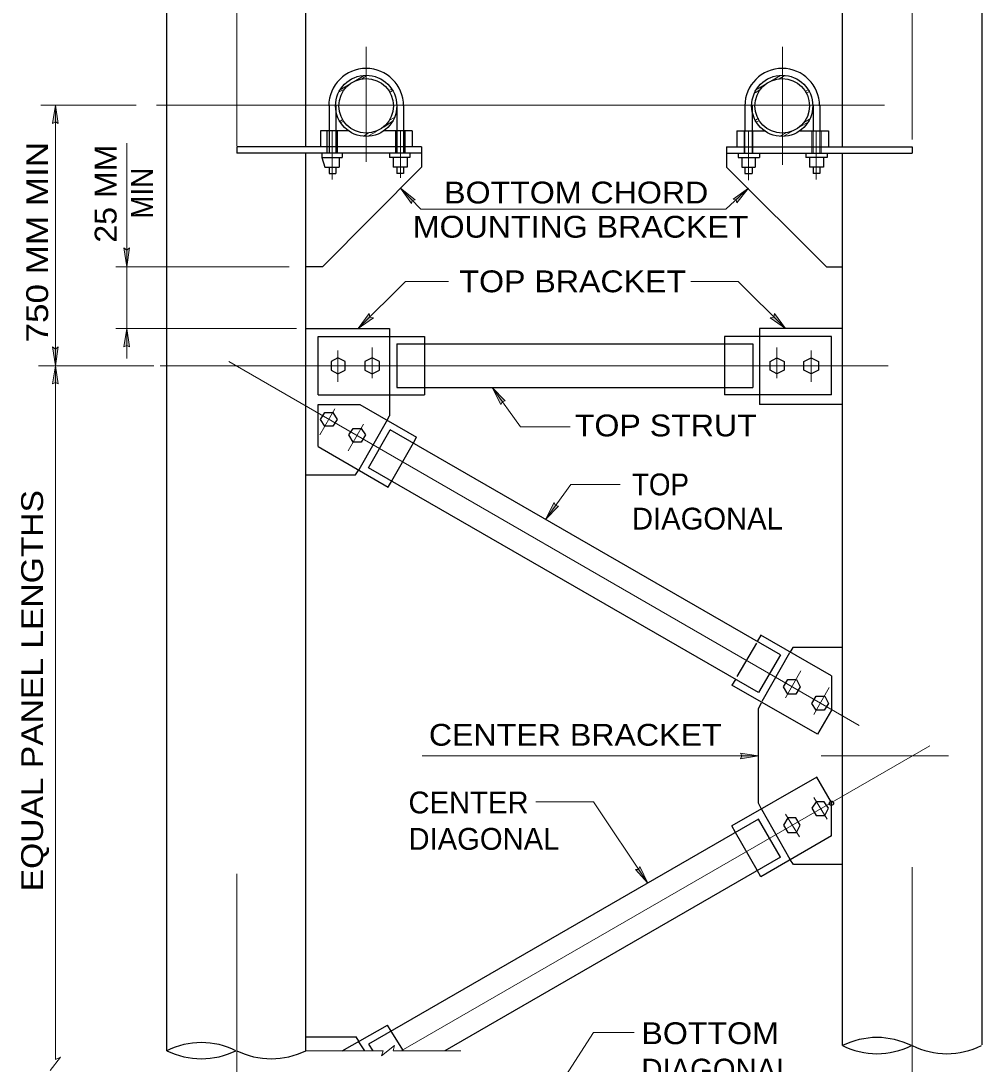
# Model space of a CAD drawing. Extents: x 312601.858 to 312602.699, y 144420.109 to 144420.704.
# Drawn here: x 312601.9368 to 312602.0688, y 144420.4227 to 144420.566 of the extents above; entities that cross this region are included whole.
import ezdxf
from ezdxf.enums import TextEntityAlignment as Align

# ---------------------------------------------------------------- set-up
doc = ezdxf.new("R2010")
doc.units = 0
doc.header["$LTSCALE"] = 0.0012
doc.header["$PDMODE"] = 32
doc.header["$PDSIZE"] = 0.0006
for name, pattern in [('DOT_DASHED', [7.7, 5, -1.2, 0.3, -1.2]), ('LONG_DASHED', [7.5, 6, -1.5]), ('MEDIUM_DASHED', [4.5, 3, -1.5])]:
    doc.linetypes.add(name, pattern=pattern)
for name, color, linetype, lineweight in [('1', 7, 'Continuous', 25), ('2', 7, 'Continuous', 13), ('39', 7, 'Continuous', 13)]:
    doc.layers.add(name, color=color, linetype=linetype, lineweight=lineweight)

msp = doc.modelspace()

# ---------------------------------------------------------------- hatches: boundary and pattern name
at = {"layer": '39'}
for points in [[(312601.9415, 144420.5521), (312601.9411, 144420.5519), (312601.9415, 144420.5544), (312601.9419, 144420.5519)], [(312601.9905, 144420.5413), (312601.9904, 144420.5409), (312601.9889, 144420.543), (312601.9909, 144420.5414)], [(312602.035, 144420.5414), (312602.0346, 144420.5415), (312602.0367, 144420.543), (312602.0351, 144420.541)], [(312601.9513, 144420.5345), (312601.9517, 144420.5348), (312601.9513, 144420.5322), (312601.9509, 144420.5348)], [(312601.9847, 144420.5253), (312601.9852, 144420.5252), (312601.9831, 144420.5237), (312601.9846, 144420.5258)], [(312602.0402, 144420.5253), (312602.0403, 144420.5258), (312602.0418, 144420.5237), (312602.0397, 144420.5252)], [(312601.9513, 144420.5214), (312601.9509, 144420.5212), (312601.9513, 144420.5237), (312601.9517, 144420.5212)], [(312601.9415, 144420.5209), (312601.9419, 144420.5212), (312601.9415, 144420.5186), (312601.9411, 144420.5212)], [(312601.9415, 144420.5163), (312601.9411, 144420.5161), (312601.9415, 144420.5186), (312601.9419, 144420.5161)], [(312602.0029, 144420.5137), (312602.0027, 144420.5133), (312602.0015, 144420.5156), (312602.0033, 144420.5138)], [(312602.0102, 144420.4994), (312602.0106, 144420.4993), (312602.0088, 144420.4975), (312602.01, 144420.4998)], [(312602.0358, 144420.465), (312602.0356, 144420.4654), (312602.0381, 144420.465), (312602.0356, 144420.4646)], [(312602.0216, 144420.4494), (312602.0218, 144420.4498), (312602.0229, 144420.4475), (312602.0212, 144420.4494)], [(312602.0216, 144420.4494), (312602.0218, 144420.4498), (312602.0229, 144420.4475), (312602.0212, 144420.4494)]]:
    msp.add_hatch(color=256, dxfattribs=at).paths.add_polyline_path(points)

# ---------------------------------------------------------------- linework, layer by layer
at = {"layer": '1'}
for p, q in [((312601.9568, 144420.4245), (312601.9568, 144420.6043)), ((312601.9759, 144420.5487), (312601.9759, 144420.6043)), ((312602.0496, 144420.5487), (312602.0496, 144420.6043)), ((312602.0688, 144420.4253), (312602.0688, 144420.6044)), ((312601.9791, 144420.5544), (312601.9791, 144420.5509)), ((312601.98, 144420.5544), (312601.98, 144420.5509)), ((312601.9884, 144420.5544), (312601.9884, 144420.5509)), ((312601.9893, 144420.5544), (312601.9893, 144420.5509)), ((312602.0362, 144420.5544), (312602.0362, 144420.5509)), ((312602.0372, 144420.5544), (312602.0372, 144420.5509)), ((312602.0456, 144420.5544), (312602.0456, 144420.5509)), ((312602.0465, 144420.5544), (312602.0465, 144420.5509)), ((312601.9818, 144420.5509), (312601.9779, 144420.5509)), ((312601.9779, 144420.5509), (312601.9779, 144420.5487)), ((312601.9905, 144420.5509), (312601.9866, 144420.5509)), ((312601.9905, 144420.5509), (312601.9905, 144420.5487)), ((312602.0351, 144420.5509), (312602.0389, 144420.5509)), ((312602.0351, 144420.5509), (312602.0351, 144420.5487)), ((312602.0438, 144420.5509), (312602.0477, 144420.5509)), ((312602.0477, 144420.5509), (312602.0477, 144420.5487)), ((312601.9918, 144420.5487), (312601.9664, 144420.5487)), ((312601.9664, 144420.5487), (312601.9664, 144420.5478)), ((312601.9918, 144420.5487), (312601.9918, 144420.5459)), ((312602.0337, 144420.5487), (312602.0592, 144420.5487)), ((312602.0337, 144420.5487), (312602.0337, 144420.5459)), ((312602.0592, 144420.5487), (312602.0592, 144420.5478)), ((312601.9918, 144420.5478), (312601.9664, 144420.5478)), ((312601.9759, 144420.4245), (312601.9759, 144420.5478)), ((312601.9781, 144420.5472), (312601.9809, 144420.5472)), ((312601.9805, 144420.5472), (312601.9805, 144420.5459)), ((312601.9809, 144420.5478), (312601.9809, 144420.5472)), ((312601.9874, 144420.5478), (312601.9874, 144420.5472)), ((312601.9902, 144420.5472), (312601.9874, 144420.5472)), ((312601.9879, 144420.5472), (312601.9879, 144420.5459)), ((312601.9898, 144420.5472), (312601.9898, 144420.5459)), ((312601.9902, 144420.5478), (312601.9902, 144420.5472)), ((312602.0337, 144420.5478), (312602.0592, 144420.5478)), ((312602.0353, 144420.5478), (312602.0353, 144420.5472)), ((312602.0353, 144420.5472), (312602.0382, 144420.5472)), ((312602.0358, 144420.5472), (312602.0358, 144420.5459)), ((312602.0376, 144420.5472), (312602.0376, 144420.5459)), ((312602.0382, 144420.5478), (312602.0382, 144420.5472)), ((312602.0446, 144420.5478), (312602.0446, 144420.5472)), ((312602.0475, 144420.5472), (312602.0446, 144420.5472)), ((312602.0451, 144420.5472), (312602.0451, 144420.5459)), ((312602.047, 144420.5472), (312602.047, 144420.5459)), ((312602.0475, 144420.5478), (312602.0475, 144420.5472)), ((312602.0496, 144420.4252), (312602.0496, 144420.5478)), ((312601.9782, 144420.5322), (312601.9918, 144420.5459)), ((312601.9785, 144420.5459), (312601.9805, 144420.5459)), ((312601.9791, 144420.5459), (312601.9791, 144420.545)), ((312601.98, 144420.5459), (312601.98, 144420.545)), ((312601.9898, 144420.5459), (312601.9879, 144420.5459)), ((312601.9884, 144420.5459), (312601.9884, 144420.545)), ((312601.9893, 144420.5459), (312601.9893, 144420.545)), ((312602.0474, 144420.5322), (312602.0337, 144420.5459)), ((312602.0358, 144420.5459), (312602.0376, 144420.5459)), ((312602.0362, 144420.5459), (312602.0362, 144420.545)), ((312602.0372, 144420.5459), (312602.0372, 144420.545)), ((312602.047, 144420.5459), (312602.0451, 144420.5459)), ((312602.0456, 144420.5459), (312602.0456, 144420.545)), ((312602.0465, 144420.5459), (312602.0465, 144420.545)), ((312601.9791, 144420.545), (312601.98, 144420.545)), ((312601.9893, 144420.545), (312601.9884, 144420.545)), ((312602.0362, 144420.545), (312602.0372, 144420.545)), ((312602.0465, 144420.545), (312602.0456, 144420.545)), ((312601.9782, 144420.5322), (312601.9759, 144420.5322)), ((312602.0474, 144420.5322), (312602.0496, 144420.5322)), ((312601.9759, 144420.5237), (312601.9874, 144420.5237)), ((312601.9874, 144420.5237), (312601.9874, 144420.5226)), ((312602.0496, 144420.5237), (312602.0382, 144420.5237)), ((312602.0382, 144420.5237), (312602.0382, 144420.5226)), ((312601.9776, 144420.5226), (312601.9922, 144420.5226)), ((312601.9776, 144420.5146), (312601.9776, 144420.5226)), ((312601.9922, 144420.5226), (312601.9922, 144420.5216)), ((312602.0481, 144420.5226), (312602.0334, 144420.5226)), ((312602.0334, 144420.5226), (312602.0334, 144420.5216)), ((312602.0481, 144420.5146), (312602.0481, 144420.5226)), ((312601.9884, 144420.5216), (312602.0373, 144420.5216)), ((312601.9884, 144420.5216), (312601.9884, 144420.5156)), ((312602.0373, 144420.5216), (312602.0373, 144420.5156)), ((312601.9884, 144420.5156), (312602.0373, 144420.5156)), ((312601.9922, 144420.5156), (312601.9922, 144420.5146)), ((312602.0334, 144420.5156), (312602.0334, 144420.5146)), ((312601.9776, 144420.5146), (312601.9922, 144420.5146)), ((312601.9874, 144420.5146), (312601.9874, 144420.5117)), ((312602.0481, 144420.5146), (312602.0334, 144420.5146)), ((312602.0382, 144420.5146), (312602.0382, 144420.5133)), ((312601.9776, 144420.5075), (312601.9776, 144420.5133)), ((312601.9776, 144420.5133), (312601.9833, 144420.5133)), ((312601.9833, 144420.5133), (312601.9911, 144420.5088)), ((312602.0496, 144420.5133), (312602.0382, 144420.5133)), ((312601.9871, 144420.5112), (312601.9874, 144420.5117)), ((312601.9845, 144420.5046), (312601.9875, 144420.5098)), ((312602.0411, 144420.4789), (312601.9875, 144420.5098)), ((312601.9907, 144420.508), (312601.9911, 144420.5088)), ((312601.9776, 144420.5075), (312601.9872, 144420.5019)), ((312601.9759, 144420.5036), (312601.9827, 144420.5036)), ((312601.9827, 144420.5036), (312601.9832, 144420.5043)), ((312602.0381, 144420.4737), (312601.9845, 144420.5046)), ((312601.9872, 144420.5019), (312601.9877, 144420.5028)), ((312602.0384, 144420.4816), (312602.0379, 144420.4807)), ((312602.0481, 144420.476), (312602.0384, 144420.4816)), ((312602.0428, 144420.4799), (312602.0424, 144420.4792)), ((312602.0496, 144420.4799), (312602.0428, 144420.4799)), ((312602.0411, 144420.4789), (312602.0381, 144420.4737)), ((312602.0349, 144420.4755), (312602.0344, 144420.4747)), ((312602.0481, 144420.476), (312602.0481, 144420.4713)), ((312602.0462, 144420.468), (312602.0344, 144420.4747)), ((312602.0381, 144420.4715), (312602.0385, 144420.4723)), ((312602.0381, 144420.4585), (312602.0381, 144420.4715)), ((312602.0481, 144420.4713), (312602.0462, 144420.468)), ((312602.0461, 144420.4621), (312602.0344, 144420.4554)), ((312602.0481, 144420.4586), (312602.0461, 144420.4621)), ((312602.0385, 144420.4577), (312602.0381, 144420.4585)), ((312602.0481, 144420.454), (312602.0481, 144420.4586)), ((312602.0381, 144420.4563), (312601.9845, 144420.4254)), ((312602.0411, 144420.4511), (312602.0381, 144420.4563)), ((312602.0349, 144420.4545), (312602.0344, 144420.4554)), ((312602.0481, 144420.454), (312602.0384, 144420.4484)), ((312602.0411, 144420.4511), (312601.995, 144420.4245)), ((312602.0429, 144420.4501), (312602.0424, 144420.4508)), ((312602.0384, 144420.4484), (312602.0379, 144420.4493)), ((312602.0496, 144420.4501), (312602.0429, 144420.4501)), ((312601.9809, 144420.4245), (312601.9871, 144420.428)), ((312601.9876, 144420.4272), (312601.9871, 144420.428)), ((312601.9759, 144420.4264), (312601.9828, 144420.4264)), ((312601.9832, 144420.4258), (312601.9828, 144420.4264)), ((312601.9845, 144420.4254), (312601.9851, 144420.4245))]:
    msp.add_line(p, q, dxfattribs=at)
at = {"layer": '1', "linetype": 'DOT_DASHED', "lineweight": 13}
for p, q in [((312601.9842, 144420.5624), (312601.9842, 144420.5466)), ((312602.0414, 144420.5624), (312602.0414, 144420.5462)), ((312601.9554, 144420.5544), (312602.0637, 144420.5544)), ((312601.9795, 144420.5442), (312601.9795, 144420.5509)), ((312601.9889, 144420.5444), (312601.9889, 144420.5509)), ((312602.0367, 144420.5441), (312602.0367, 144420.5509)), ((312602.046, 144420.5442), (312602.046, 144420.5509)), ((312601.985, 144420.5169), (312601.985, 144420.5211)), ((312602.0406, 144420.5169), (312602.0406, 144420.5211)), ((312601.9803, 144420.5164), (312601.9803, 144420.5207)), ((312602.0453, 144420.5164), (312602.0453, 144420.5207)), ((312601.9559, 144420.5186), (312602.062, 144420.5186)), ((312601.9653, 144420.5192), (312602.0616, 144420.4636)), ((312601.9799, 144420.5127), (312601.9778, 144420.5091)), ((312601.9838, 144420.5106), (312601.9817, 144420.5069)), ((312602.0418, 144420.473), (312602.0439, 144420.4767)), ((312602.0457, 144420.4707), (312602.0478, 144420.4744)), ((312601.989, 144420.4245), (312602.0616, 144420.4664)), ((312602.0467, 144420.465), (312602.0642, 144420.465)), ((312602.0457, 144420.4593), (312602.0475, 144420.4563)), ((312602.0418, 144420.457), (312602.0437, 144420.4539))]:
    msp.add_line(p, q, dxfattribs=at)
at = {"layer": '1', "lineweight": 13}
for p, q in [((312601.9806, 144420.5565), (312601.9839, 144420.5585)), ((312601.9836, 144420.558), (312601.9843, 144420.5585)), ((312602.0379, 144420.5566), (312602.0411, 144420.5585)), ((312602.0409, 144420.558), (312602.0417, 144420.5585)), ((312601.9804, 144420.5562), (312601.9812, 144420.5566)), ((312601.9873, 144420.5564), (312601.9877, 144420.5566)), ((312602.0376, 144420.5561), (312602.0384, 144420.5566)), ((312601.9875, 144420.5562), (312601.9878, 144420.5564)), ((312602.0445, 144420.5563), (312602.0449, 144420.5565)), ((312602.0447, 144420.5561), (312602.0451, 144420.5563)), ((312601.9395, 144420.5544), (312601.9526, 144420.5544)), ((312601.9806, 144420.5522), (312601.9809, 144420.5524)), ((312601.9873, 144420.5523), (312601.9881, 144420.5527)), ((312602.0376, 144420.5523), (312602.0381, 144420.5526)), ((312602.0378, 144420.5521), (312602.0382, 144420.5523)), ((312602.0443, 144420.552), (312602.0451, 144420.5525)), ((312601.9807, 144420.552), (312601.9811, 144420.5522)), ((312601.9866, 144420.5514), (312601.9878, 144420.5522)), ((312602.0416, 144420.5502), (312602.0448, 144420.552)), ((312601.9839, 144420.5502), (312601.9845, 144420.5506)), ((312601.9845, 144420.5502), (312601.9856, 144420.5508)), ((312602.0411, 144420.5502), (312602.0419, 144420.5506)), ((312601.9889, 144420.543), (312601.9917, 144420.5401)), ((312602.0336, 144420.5401), (312602.0367, 144420.543)), ((312601.9917, 144420.5401), (312602.0336, 144420.5401)), ((312601.9736, 144420.5322), (312601.9498, 144420.5322)), ((312601.9831, 144420.5237), (312601.9896, 144420.5302)), ((312601.9896, 144420.5302), (312601.9955, 144420.5302)), ((312602.0288, 144420.5302), (312602.0353, 144420.5302)), ((312602.0418, 144420.5237), (312602.0353, 144420.5302)), ((312601.9498, 144420.5237), (312601.9746, 144420.5237)), ((312601.9513, 144420.5237), (312601.9513, 144420.5196)), ((312601.9392, 144420.5186), (312601.955, 144420.5186)), ((312602.0054, 144420.5102), (312602.0015, 144420.5156)), ((312602.0054, 144420.5102), (312602.0122, 144420.5102)), ((312602.0088, 144420.4975), (312602.0123, 144420.5023)), ((312602.0123, 144420.5023), (312602.0191, 144420.5023)), ((312601.9919, 144420.465), (312602.0381, 144420.465)), ((312601.9881, 144420.4252), (312601.9863, 144420.4238)), ((312601.9881, 144420.4252), (312601.9879, 144420.4245)), ((312601.9422, 144420.4236), (312601.9408, 144420.4218)), ((312601.9422, 144420.4236), (312601.9415, 144420.4233)), ((312601.9759, 144420.4245), (312601.9865, 144420.4245)), ((312601.9865, 144420.4245), (312601.9863, 144420.4238)), ((312601.9879, 144420.4245), (312601.9972, 144420.4245))]:
    msp.add_line(p, q, dxfattribs=at)
at = {"layer": '1', "linetype": 'LONG_DASHED'}
for p, q in [((312601.9788, 144420.5509), (312601.9788, 144420.5478)), ((312601.9791, 144420.5509), (312601.9791, 144420.5478)), ((312601.98, 144420.5509), (312601.98, 144420.5478)), ((312601.9802, 144420.5509), (312601.9802, 144420.5478)), ((312601.9882, 144420.5509), (312601.9882, 144420.5478)), ((312601.9884, 144420.5509), (312601.9884, 144420.5478)), ((312601.9893, 144420.5509), (312601.9893, 144420.5478)), ((312601.9895, 144420.5509), (312601.9895, 144420.5478))]:
    msp.add_line(p, q, dxfattribs=at)
at = {"layer": '1', "linetype": 'LONG_DASHED', "lineweight": 13}
for p, q in [((312602.0361, 144420.5509), (312602.0361, 144420.5478)), ((312602.0362, 144420.5509), (312602.0362, 144420.5478)), ((312602.0372, 144420.5509), (312602.0372, 144420.5478)), ((312602.0373, 144420.5509), (312602.0373, 144420.5478)), ((312602.0454, 144420.5509), (312602.0454, 144420.5478)), ((312602.0456, 144420.5509), (312602.0456, 144420.5478)), ((312602.0465, 144420.5509), (312602.0465, 144420.5478)), ((312602.0467, 144420.5509), (312602.0467, 144420.5478))]:
    msp.add_line(p, q, dxfattribs=at)
at = {"layer": '1', "linetype": 'MEDIUM_DASHED'}
for p, q in [((312601.9874, 144420.5226), (312601.9874, 144420.5146)), ((312602.0382, 144420.5226), (312602.0382, 144420.5146)), ((312601.9922, 144420.5216), (312601.9922, 144420.5156)), ((312602.0334, 144420.5216), (312602.0334, 144420.5156)), ((312601.9871, 144420.5112), (312601.9832, 144420.5043)), ((312601.9877, 144420.5028), (312601.9907, 144420.508)), ((312602.0378, 144420.4805), (312602.0351, 144420.4759)), ((312602.0386, 144420.4725), (312602.0424, 144420.4792)), ((312602.0385, 144420.4577), (312602.0424, 144420.4508)), ((312602.0379, 144420.4493), (312602.0349, 144420.4545)), ((312601.9893, 144420.4245), (312601.9876, 144420.4272)), ((312601.984, 144420.4245), (312601.9832, 144420.4257))]:
    msp.add_line(p, q, dxfattribs=at)
at = {"layer": '1', "lineweight": 13}
for points in [[(312601.9415, 144420.4233), (312601.9415, 144420.5186), (312601.9415, 144420.5544)], [(312601.9513, 144420.5492), (312601.9513, 144420.5322), (312601.9513, 144420.5237)], [(312602.0075, 144420.4587), (312602.0154, 144420.4587), (312602.0229, 144420.4475)], [(312602.021, 144420.427), (312602.0154, 144420.427), (312602.007, 144420.4139)]]:
    msp.add_lwpolyline(points, dxfattribs=at)
at = {"layer": '1'}
msp.add_lwpolyline([(312601.9781, 144420.5478), (312601.9781, 144420.5472), (312601.9785, 144420.5459)], dxfattribs=at)
for points in [[(312601.9813, 144420.518), (312601.9813, 144420.5192), (312601.9803, 144420.5197), (312601.9794, 144420.5192), (312601.9794, 144420.518), (312601.9803, 144420.5175)], [(312601.986, 144420.518), (312601.986, 144420.5192), (312601.985, 144420.5197), (312601.984, 144420.5192), (312601.984, 144420.518), (312601.985, 144420.5175)], [(312602.0397, 144420.518), (312602.0397, 144420.5192), (312602.0406, 144420.5197), (312602.0416, 144420.5192), (312602.0416, 144420.518), (312602.0406, 144420.5175)], [(312602.0443, 144420.518), (312602.0443, 144420.5192), (312602.0453, 144420.5197), (312602.0463, 144420.5192), (312602.0463, 144420.518), (312602.0453, 144420.5175)], [(312601.9802, 144420.5112), (312601.9796, 144420.5103), (312601.9785, 144420.5103), (312601.9779, 144420.5112), (312601.9785, 144420.5122), (312601.9796, 144420.5122)], [(312601.9841, 144420.5091), (312601.9835, 144420.5081), (312601.9824, 144420.5081), (312601.9818, 144420.5091), (312601.9824, 144420.51), (312601.9835, 144420.51)], [(312602.0415, 144420.4745), (312602.0421, 144420.4755), (312602.0433, 144420.4755), (312602.0438, 144420.4745), (312602.0432, 144420.4735), (312602.0421, 144420.4735)], [(312602.0454, 144420.4722), (312602.046, 144420.4732), (312602.0472, 144420.4732), (312602.0477, 144420.4722), (312602.0471, 144420.4713), (312602.046, 144420.4713)], [(312602.0454, 144420.4578), (312602.046, 144420.4568), (312602.0472, 144420.4568), (312602.0477, 144420.4578), (312602.0471, 144420.4587), (312602.046, 144420.4587)], [(312602.0415, 144420.4555), (312602.0421, 144420.4545), (312602.0433, 144420.4545), (312602.0438, 144420.4555), (312602.0432, 144420.4565), (312602.0421, 144420.4565)]]:
    msp.add_lwpolyline(points, close=True, dxfattribs=at)
for centre, radius in [((312601.984187, 144420.554312), 0.0042), ((312601.984187, 144420.554312), 0.00375), ((312602.041337, 144420.554312), 0.0042), ((312602.041337, 144420.554312), 0.00375)]:
    msp.add_circle(centre, radius, dxfattribs=at)
for centre in [(312601.984187, 144420.554312), (312602.041337, 144420.554312)]:
    msp.add_arc(centre, 0.005137, 0, 180, dxfattribs=at)
msp.add_point((312602.0481, 144420.4585), dxfattribs=at)
at = {"layer": '2', "linetype": 'DOT_DASHED'}
for p, q in [((312602.0592, 144420.3497), (312602.0592, 144420.6313)), ((312601.9664, 144420.3488), (312601.9664, 144420.631))]:
    msp.add_line(p, q, dxfattribs=at)
at = {"layer": '2', "lineweight": 25}
for centre, start, end in [((312602.05435, 144420.415586), 63.70649, 116.29351), ((312601.96155, 144420.414886), 63.70649, 116.29351), ((312602.05435, 144420.434814), 243.70649, 296.29351), ((312602.06395, 144420.434814), 243.70649, 296.29351), ((312601.96155, 144420.434114), 243.70649, 296.29351), ((312601.97115, 144420.434114), 243.70649, 296.29351)]:
    msp.add_arc(centre, 0.010723, start, end, dxfattribs=at)
at = {"layer": '39'}
for points in [[(312601.9415, 144420.5521), (312601.9411, 144420.5519), (312601.9415, 144420.5544), (312601.9419, 144420.5519)], [(312601.9905, 144420.5413), (312601.9904, 144420.5409), (312601.9889, 144420.543), (312601.9909, 144420.5414)], [(312602.035, 144420.5414), (312602.0346, 144420.5415), (312602.0367, 144420.543), (312602.0351, 144420.541)], [(312601.9513, 144420.5345), (312601.9517, 144420.5348), (312601.9513, 144420.5322), (312601.9509, 144420.5348)], [(312601.9847, 144420.5253), (312601.9852, 144420.5252), (312601.9831, 144420.5237), (312601.9846, 144420.5258)], [(312602.0402, 144420.5253), (312602.0403, 144420.5258), (312602.0418, 144420.5237), (312602.0397, 144420.5252)], [(312601.9513, 144420.5214), (312601.9509, 144420.5212), (312601.9513, 144420.5237), (312601.9517, 144420.5212)], [(312601.9415, 144420.5209), (312601.9419, 144420.5212), (312601.9415, 144420.5186), (312601.9411, 144420.5212)], [(312601.9415, 144420.5163), (312601.9411, 144420.5161), (312601.9415, 144420.5186), (312601.9419, 144420.5161)], [(312602.0029, 144420.5137), (312602.0027, 144420.5133), (312602.0015, 144420.5156), (312602.0033, 144420.5138)], [(312602.0102, 144420.4994), (312602.0106, 144420.4993), (312602.0088, 144420.4975), (312602.01, 144420.4998)], [(312602.0358, 144420.465), (312602.0356, 144420.4654), (312602.0381, 144420.465), (312602.0356, 144420.4646)], [(312602.0216, 144420.4494), (312602.0218, 144420.4498), (312602.0229, 144420.4475), (312602.0212, 144420.4494)], [(312602.0216, 144420.4494), (312602.0218, 144420.4498), (312602.0229, 144420.4475), (312602.0212, 144420.4494)]]:
    msp.add_lwpolyline(points, close=True, dxfattribs=at)

# ---------------------------------------------------------------- texts
at = {"layer": '2'}
for s, width, p in [('750 MM MIN', 1.2, (312601.9405, 144420.5218)), ('EQUAL PANEL LENGTHS', 1.15, (312601.9398, 144420.4464))]:
    msp.add_text(s, height=0.003, rotation=90, dxfattribs=dict(at, width=width)).set_placement(p)
for s, width, p in [('25 MM', 1.1, (312601.9499, 144420.54225)), ('MIN', 0.95, (312601.9549, 144420.5423))]:
    msp.add_text(s, height=0.003, rotation=90, dxfattribs=dict(at, width=width)).set_placement(p, align=Align.CENTER)
for s, width, p in [('BOTTOM CHORD', 1.1, (312601.9949, 144420.5409)), ('MOUNTING BRACKET', 1.1, (312601.9906, 144420.5362)), ('TOP BRACKET', 1.1, (312601.997, 144420.5287)), ('TOP', 0.95, (312602.0207, 144420.5008)), ('CENTER BRACKET', 1.1, (312601.9928, 144420.4664)), ('BOTTOM ', 1.1, (312602.022, 144420.4254))]:
    msp.add_text(s, height=0.003, dxfattribs=dict(at, width=width)).set_placement(p)
at = {"layer": '2', "width": 1.1}
msp.add_text('TOP STRUT', height=0.003, dxfattribs=at).set_placement((312602.02535, 144420.5089), align=Align.CENTER)
at = {"layer": '2'}
for s, p in [('DIAGONAL', (312602.0207, 144420.4961)), ('CENTER', (312601.99, 144420.4571)), ('DIAGONAL', (312601.99, 144420.4521)), ('DIAGONAL', (312602.022, 144420.4204))]:
    msp.add_text(s, height=0.003, dxfattribs=at).set_placement(p)

doc.saveas('drawing.dxf')
